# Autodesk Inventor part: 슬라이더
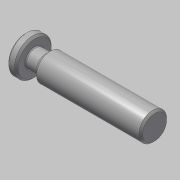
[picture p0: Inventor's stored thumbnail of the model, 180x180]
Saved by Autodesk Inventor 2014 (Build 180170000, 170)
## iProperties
Created: 2016-05
Part Number: 슬라이더
Document SubType Name: Modeling
Designer: mduedu
Density: 7.86 g/cm^3
Material: 강철, 연강
Appearance: 강철
Author: mduedu
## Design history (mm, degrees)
sketch "스케치1"
  geometry: L1 (-7.5, 0)-(62.5, 0); L2 (62.5, 0)-(62.5, 7.5); L3 (62.5, 7.5)-(0, 7.5); L4 (-7.5, 0)-(-7.5, 10); L5 (-7.5, 10)-(-2.5, 10); L6 (-2.5, 10)-(-2.5, 5); L7 (-2.5, 5)-(3.5, 5); L8 (3.5, 5)-(6, 7.5); A1 r 7.5 centre (0, 0) between (0, 7.5) and (-7.5, 0); 1 further point
  constraints: 16 end point, 3 perpendicular, 2 horizontal, 2 parallel, 2 point on circle, 2 point on line, 2 tangent, 1 centre point, 1 coincident
  dimensions: "d0" = 15 diameter of A1; "d1" = 70 distance of L1.start L1.end; "d19" = 20 diameter of L5 L1; "d20" = 10 diameter of L7 L1; "d21" = 5 distance of L4.end L5.end; "d22" = 135 deg angle of L8 L7; "d23" = 6 distance of L6.end L7.end
revolve "회전1" stored, may be unused: angle "d4" = 90 deg
chamfer "모따기2" distance "d24" = 1; stored, may be unused: second distance "d25" = 2, angle "d26" = 45 deg
fillet "모깎기1" dims "d27" = 0.5
node "솔리드1"
